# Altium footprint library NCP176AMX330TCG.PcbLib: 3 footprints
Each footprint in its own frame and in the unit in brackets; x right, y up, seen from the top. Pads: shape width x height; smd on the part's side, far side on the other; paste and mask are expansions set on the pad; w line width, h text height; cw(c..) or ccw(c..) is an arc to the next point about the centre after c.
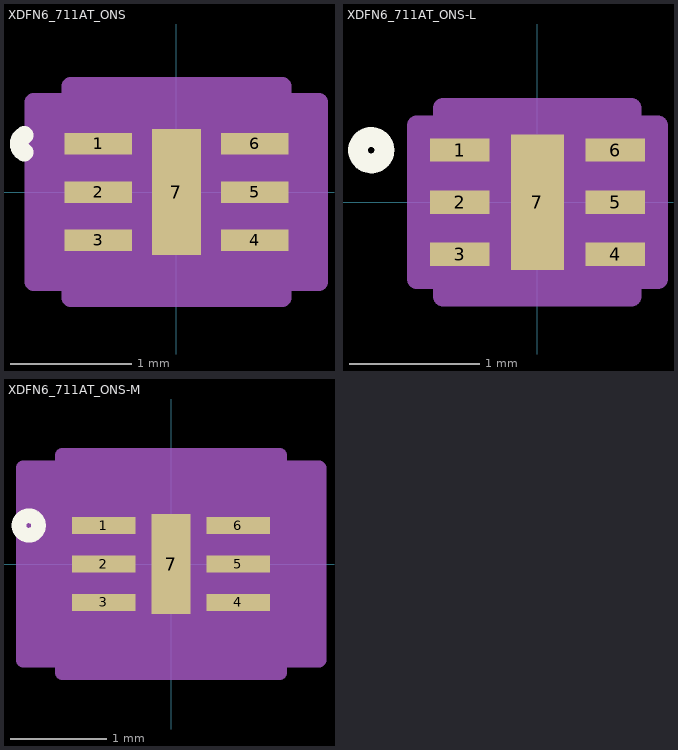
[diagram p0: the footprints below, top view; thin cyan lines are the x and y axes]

## XDFN6_711AT_ONS [mil]
pads (7):
  rect 22x7 smd paste+0 mask+0: 1(-25.5,15.75) 2(-25.5,0) 3(-25.5,-15.75) 4(25.5,-15.75) 5(25.5,0) 6(25.5,15.75)
  rect 16x41 smd paste+0 mask+0: 7(0,0)
Top Overlay:
  lines w6: -49.6,13.01 cw(c-48.37,15.75) -49.6,18.49
Mechanical 13:
  circle w6: c-14.5,15.75 r0
  lines w0: -12,24.5 ccw(c0,24.5) 12,24.5
  lines w1: -24.5,-24.5 24.5,-24.5 24.5,24.5 -24.5,24.5 -24.5,-24.5
Mechanical 15:
  region: -34.5,-29.25 -46.5,-29.25 -46.5,29.25 -34.5,29.25 -34.5,34.5 34.5,34.5 34.5,29.25 46.5,29.25 46.5,-29.25 34.5,-29.25 34.5,-34.5 -34.5,-34.5
  lines w6: -46.5,-29.25 -46.5,29.25 -34.5,29.25 -34.5,34.5 34.5,34.5 34.5,29.25 46.5,29.25 46.5,-29.25 34.5,-29.25 34.5,-34.5 -34.5,-34.5 -34.5,-29.25 -46.5,-29.25
3D body "XDFN6_711AT_ONS.step": height 18.11, standoff 0, extent -24.49,-24.49 24.49,24.49

## XDFN6_711AT_ONS-L [mil]
pads (7):
  rect 18x7 smd paste+0 mask+0: 1(-23.5,15.75) 2(-23.5,0) 3(-23.5,-15.75) 4(23.5,-15.75) 5(23.5,0) 6(23.5,15.75)
  rect 16x41 smd paste+0 mask+0: 7(0,0)
Top Overlay:
  circle w6: c-50.25,15.75 r4
Mechanical 13:
  circle w0: c-14.5,15.75 r3
  lines w0: -12,24.5 ccw(c0,24.5) 12,24.5
  lines w1: -24.5,-24.5 24.5,-24.5 24.5,24.5 -24.5,24.5 -24.5,-24.5
Mechanical 15:
  region: -28.5,-23.25 -36.5,-23.25 -36.5,23.25 -28.5,23.25 -28.5,28.5 28.5,28.5 28.5,23.25 36.5,23.25 36.5,-23.25 28.5,-23.25 28.5,-28.5 -28.5,-28.5
  lines w6: -36.5,-23.25 -36.5,23.25 -28.5,23.25 -28.5,28.5 28.5,28.5 28.5,23.25 36.5,23.25 36.5,-23.25 28.5,-23.25 28.5,-28.5 -28.5,-28.5 -28.5,-23.25 -36.5,-23.25
3D body "XDFN6_711AT_ONS.step": height 18.11, standoff 0, extent -24.49,-24.49 24.49,24.49

## XDFN6_711AT_ONS-M [mil]
pads (7):
  rect 26x7 smd paste+0 mask+0: 1(-27.5,15.75) 2(-27.5,0) 3(-27.5,-15.75) 4(27.5,-15.75) 5(27.5,0) 6(27.5,15.75)
  rect 16x41 smd paste+0 mask+0: 7(0,0)
Top Overlay:
  circle w6: c-58.25,15.75 r4
Mechanical 13:
  circle w0: c-14.5,15.75 r3
  lines w0: -12,24.5 ccw(c0,24.5) 12,24.5
  lines w1: -24.5,-24.5 24.5,-24.5 24.5,24.5 -24.5,24.5 -24.5,-24.5
Mechanical 15:
  region: -44.5,-39.25 -60.5,-39.25 -60.5,39.25 -44.5,39.25 -44.5,44.5 44.5,44.5 44.5,39.25 60.5,39.25 60.5,-39.25 44.5,-39.25 44.5,-44.5 -44.5,-44.5
  lines w6: -60.5,-39.25 -60.5,39.25 -44.5,39.25 -44.5,44.5 44.5,44.5 44.5,39.25 60.5,39.25 60.5,-39.25 44.5,-39.25 44.5,-44.5 -44.5,-44.5 -44.5,-39.25 -60.5,-39.25
3D body "XDFN6_711AT_ONS.step": height 18.11, standoff 0, extent -24.49,-24.49 24.49,24.49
